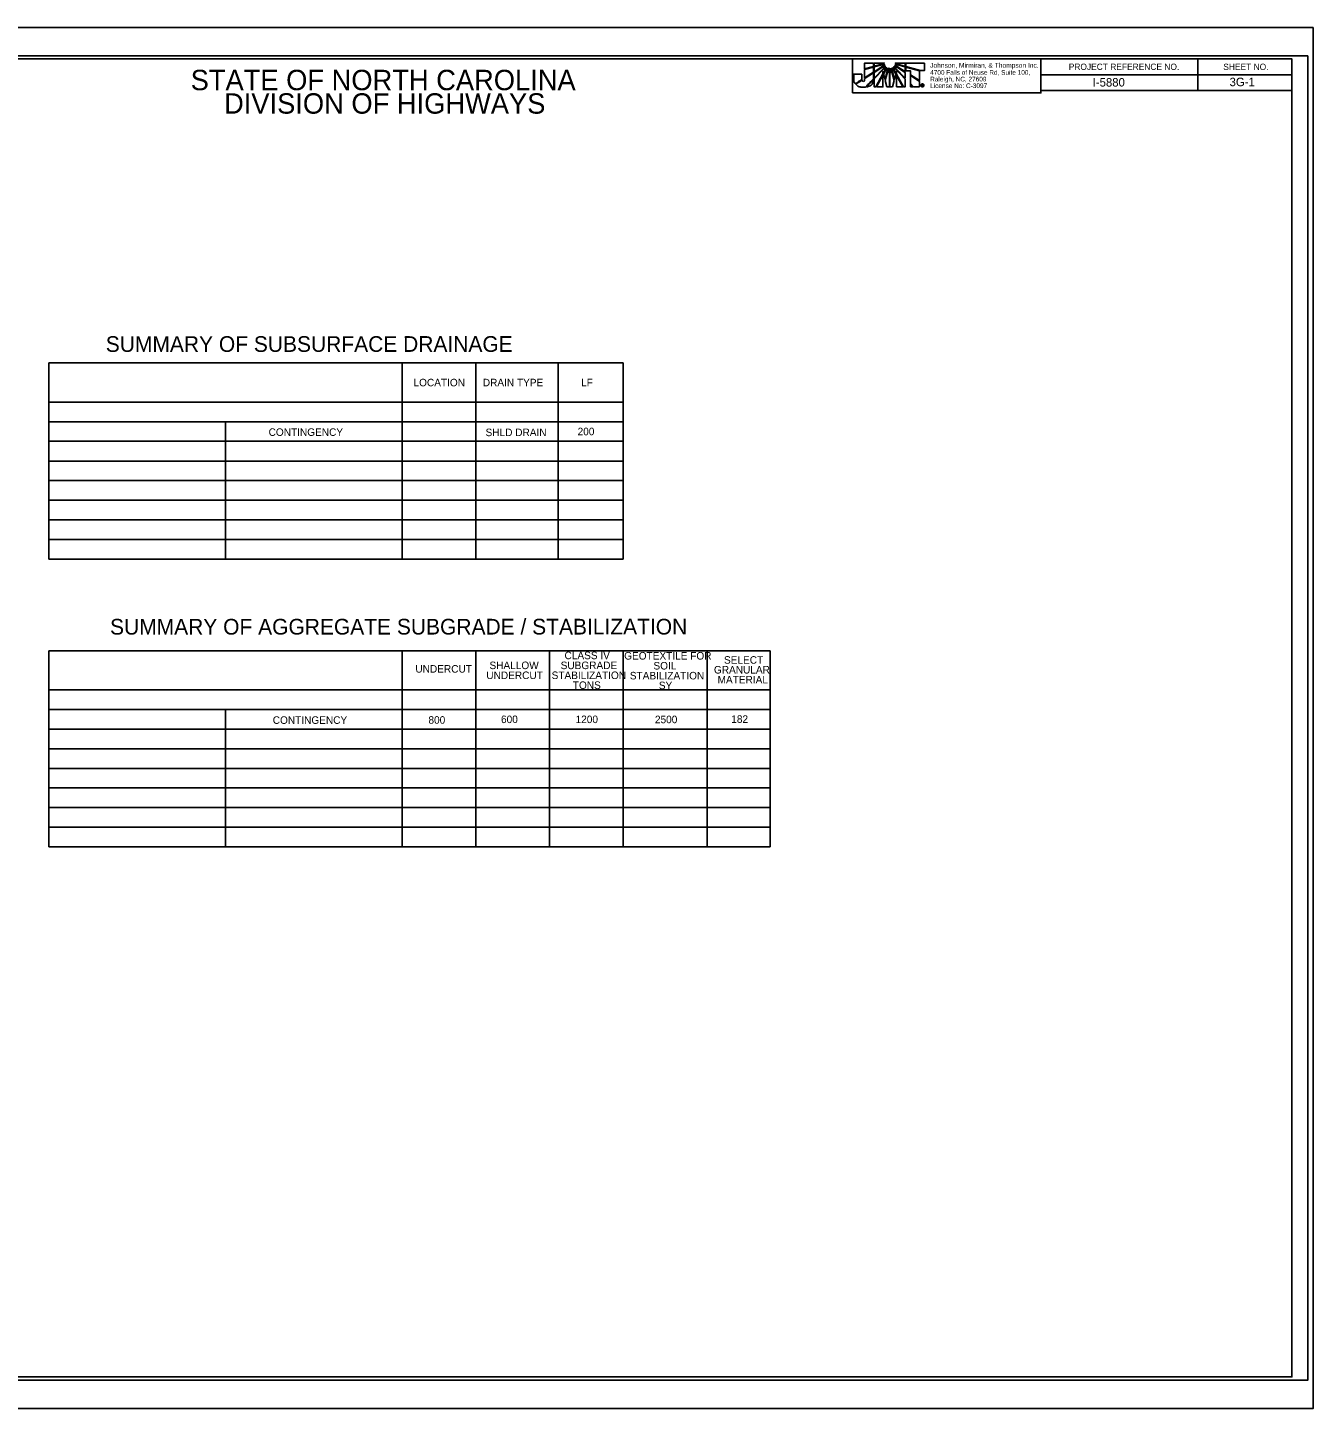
# Model space of a CAD drawing. Extents: x 573692 to 577281, y -53325 to -51406.
# Drawn here: x 576257 to 577281, y -53325 to -52225 of the extents above; entities that cross this region are included whole.
import ezdxf

# ---------------------------------------------------------------- set-up
doc = ezdxf.new("R2010")
doc.units = 0
for name, color, linetype in [('Exist Profile Cell', 7, 'Continuous'), ('Exist Vertical Profile Ground Line', 7, 'Continuous'), ('Exist Vertical Profile Horizontal Axis Label Major', 7, 'Continuous'), ('Prop Conc Island Cover', 7, 'Continuous'), ('Prop EOT', 7, 'Continuous'), ('Prop Horizontal Alignment', 7, 'Continuous'), ('Sheet North Arrow CELL', 7, 'Continuous')]:
    doc.layers.add(name, color=color, linetype=linetype)

msp = doc.modelspace()

# ---------------------------------------------------------------- linework, layer by layer
at = {"layer": 'Exist Profile Cell'}
msp.add_lwpolyline([(577280.6, -52224.8), (575596.6, -52224.8), (575596.6, -53324.8), (577280.6, -53324.8)], close=True, dxfattribs=at)
at = {"layer": 'Exist Vertical Profile Horizontal Axis Label Major'}
for p, q in [((577280.6, -52224.8), (575596.6, -52224.8)), ((575596.6, -53324.8), (577280.6, -53324.8))]:
    msp.add_line(p, q, dxfattribs=at)
at = {"layer": 'Prop Conc Island Cover'}
msp.add_lwpolyline([(577276.1, -52247.3), (575609.6, -52247.3), (575609.6, -53302.4), (577276.1, -53302.4)], close=True, dxfattribs=at)
at = {"layer": 'Prop EOT'}
for p, q in [((577188.6, -52249.9), (577188.6, -52274.9)), ((577063.6, -52262.4), (577263.6, -52262.4)), ((577063.6, -52274.9), (577263.6, -52274.9)), ((576516.2, -52491.9), (576516.2, -52491.9)), ((576497, -52492), (576497, -52492)), ((576504.9, -52492.1), (576504.9, -52492.1)), ((576523.2, -52492), (576523.2, -52492)), ((576497, -52721.3), (576497, -52721.3)), ((576504.9, -52721.4), (576504.9, -52721.4)), ((576516.2, -52721.2), (576516.2, -52721.2)), ((576523.2, -52721.3), (576523.2, -52721.3))]:
    msp.add_line(p, q, dxfattribs=at)
for points in [[(577263.6, -52249.8), (575763.6, -52249.8), (575763.6, -53299.8), (577263.6, -53299.8)], [(577063.6, -52249.8), (577263.6, -52249.8), (577263.6, -52274.9), (577063.6, -52274.9)]]:
    msp.add_lwpolyline(points, close=True, dxfattribs=at)
at = {"layer": 'Prop Horizontal Alignment'}
for p, q in [((576930.2, -52253.2), (576923.1, -52253.2)), ((576923.1, -52253.2), (576923.1, -52257.8)), ((576923.1, -52257.8), (576930.2, -52255.9)), ((576930.2, -52256.4), (576923.1, -52258.3)), ((576923.1, -52258.3), (576923.1, -52264.9)), ((576923.1, -52264.9), (576930.2, -52260.4)), ((576930.2, -52255.9), (576930.2, -52253.2)), ((576930.2, -52260.4), (576930.2, -52256.4)), ((576938.8, -52253.1), (576930.9, -52253.1)), ((576930.9, -52253.1), (576930.9, -52255.6)), ((576930.9, -52255.6), (576936.8, -52254)), ((576936.8, -52254.5), (576930.9, -52256.2)), ((576930.9, -52256.2), (576930.9, -52260)), ((576930.9, -52260), (576936.2, -52256.6)), ((576937, -52256.7), (576930.9, -52260.6)), ((576930.9, -52265), (576938.3, -52257.3)), ((576938.6, -52257.6), (576930.9, -52265.7)), ((576930.9, -52260.6), (576930.9, -52265)), ((576936.2, -52256.6), (576939.1, -52254.3)), ((576936.8, -52254), (576938.8, -52253.1)), ((576939.1, -52254.3), (576936.8, -52254.5)), ((576939.6, -52255.4), (576937, -52256.7)), ((576937.8, -52261.7), (576937.8, -52259.9)), ((576937.8, -52259.9), (576938.1, -52261.1)), ((576938.1, -52261.1), (576939.6, -52258.4)), ((576938.3, -52257.3), (576939.6, -52255.4)), ((576940.1, -52258.6), (576938.3, -52261.8)), ((576940.4, -52256.2), (576938.6, -52257.6)), ((576939.5, -52266), (576941.3, -52259)), ((576939.6, -52258.4), (576940.4, -52256.2)), ((576941.7, -52259.4), (576939.7, -52267)), ((576941.5, -52256.8), (576940.1, -52258.6)), ((576941.3, -52259), (576941.5, -52256.8)), ((576942.6, -52257.1), (576941.7, -52259.4)), ((576942.9, -52262.7), (576942.6, -52257.1)), ((576943.8, -52257.1), (576943.4, -52262.7)), ((576944.7, -52259.4), (576943.8, -52257.1)), ((576946.7, -52267.1), (576944.7, -52259.4)), ((576944.9, -52256.8), (576945.1, -52259.1)), ((576946.3, -52258.6), (576944.9, -52256.8)), ((576945.1, -52259.1), (576947, -52266.2)), ((576945.9, -52256.2), (576946.8, -52258.4)), ((576947.8, -52257.6), (576945.9, -52256.2)), ((576948.1, -52261.9), (576946.3, -52258.6)), ((576946.7, -52255.4), (576948.1, -52257.3)), ((576949.4, -52256.7), (576946.7, -52255.4)), ((576946.8, -52258.4), (576948.3, -52261.2)), ((576947.3, -52254.3), (576950.3, -52256.7)), ((576949.5, -52254.5), (576947.3, -52254.3)), ((576955.5, -52253.1), (576947.7, -52253.1)), ((576947.7, -52253.1), (576949.7, -52254)), ((576955.5, -52265.8), (576947.8, -52257.6)), ((576948.1, -52257.3), (576955.5, -52265)), ((576948.3, -52261.2), (576948.6, -52259.8)), ((576948.6, -52259.8), (576948.6, -52261.9)), ((576955.5, -52260.5), (576949.4, -52256.7)), ((576955.5, -52256.2), (576949.5, -52254.5)), ((576949.7, -52254), (576955.5, -52255.7)), ((576950.3, -52256.7), (576955.5, -52259.9)), ((576955.5, -52255.7), (576955.5, -52253.1)), ((576955.5, -52259.9), (576955.5, -52256.2)), ((576955.5, -52265), (576955.5, -52260.5)), ((576970.8, -52253.1), (576956, -52253.1)), ((576956, -52253.1), (576956, -52255.8)), ((576956, -52255.8), (576956, -52255.9)), ((576956, -52255.9), (576967.7, -52259.1)), ((576956, -52256.3), (576956, -52256.3)), ((576956, -52256.3), (576956, -52259.2)), ((576966.9, -52259.4), (576956, -52256.3)), ((576956, -52259.2), (576959.7, -52259.2)), ((576959.7, -52259.2), (576959.7, -52262.5)), ((576966.9, -52267.1), (576966.9, -52259.4)), ((576967.7, -52259.1), (576970.8, -52259.1)), ((576970.8, -52259.1), (576970.8, -52253.1)), ((576930.9, -52265.7), (576930.9, -52272.1)), ((576932.1, -52272.1), (576937.8, -52261.7)), ((576937.8, -52262.7), (576932.6, -52272.1)), ((576937.8, -52272.1), (576937.8, -52262.7)), ((576938.3, -52261.8), (576939.5, -52266)), ((576939.7, -52267), (576941, -52272)), ((576942.9, -52272), (576942.9, -52262.7)), ((576943.4, -52262.7), (576943.4, -52272)), ((576945.4, -52272), (576946.7, -52267.1)), ((576947, -52266.2), (576948.1, -52261.9)), ((576948.6, -52261.9), (576954.2, -52272.1)), ((576953.7, -52272), (576948.6, -52262.9)), ((576948.6, -52262.9), (576948.6, -52272)), ((576955.5, -52272.1), (576955.5, -52265.8)), ((576959.7, -52262.5), (576966.9, -52267.1)), ((576959.7, -52263.1), (576959.7, -52269.4)), ((576966.9, -52267.7), (576959.7, -52263.1)), ((576959.7, -52269.4), (576962.2, -52272)), ((576961.5, -52272), (576959.7, -52270.1)), ((576959.7, -52270.1), (576959.7, -52272)), ((576966.9, -52272), (576966.9, -52267.7)), ((576968.8, -52271.4), (576968.8, -52270.3)), ((576968.8, -52270.3), (576969.2, -52270.3)), ((576969, -52271.4), (576968.8, -52271.4)), ((576969.2, -52270.5), (576969, -52270.5)), ((576969, -52270.5), (576969, -52270.8)), ((576969, -52270.8), (576969.2, -52270.8)), ((576969.2, -52271), (576969, -52271)), ((576969, -52271), (576969, -52271.4)), ((576969.2, -52269.7), (576969.2, -52269.9)), ((576969.2, -52269.9), (576969.2, -52269.7)), ((576969.2, -52270.3), (576969.2, -52270.5)), ((576969.2, -52270.5), (576969.2, -52270.3)), ((576969.2, -52270.3), (576969.3, -52270.3)), ((576969.2, -52270.5), (576969.2, -52270.5)), ((576969.2, -52270.8), (576969.2, -52271)), ((576969.2, -52271), (576969.2, -52270.8)), ((576969.2, -52270.8), (576969.2, -52270.8)), ((576969.2, -52271), (576969.2, -52271)), ((576969.2, -52271.8), (576969.2, -52272)), ((576969.2, -52272), (576969.2, -52271.8)), ((576969.2, -52271.8), (576969.2, -52271.8)), ((576930.9, -52272.1), (576932.1, -52272.1)), ((576932.6, -52272.1), (576937.8, -52272.1)), ((576941, -52272), (576942.9, -52272)), ((576943.4, -52272), (576945.4, -52272)), ((576948.6, -52272), (576953.7, -52272)), ((576954.2, -52272.1), (576955.5, -52272.1)), ((576959.7, -52272), (576961.5, -52272)), ((576962.2, -52272), (576966.9, -52272)), ((576969.2, -52272), (576969.2, -52272))]:
    msp.add_line(p, q, dxfattribs=at)
msp.add_lwpolyline([(576913.6, -52276.9), (577063.6, -52276.9), (577063.6, -52249.8), (576913.6, -52249.8)], close=True, dxfattribs=at)
for points in [[(576923.1, -52257.8), (576930.2, -52255.9), (576930.2, -52253.2), (576923.1, -52253.2), (576923.1, -52257.8)], [(576923.1, -52264.9), (576930.2, -52260.4), (576930.2, -52256.4), (576923.1, -52258.3), (576923.1, -52264.9)], [(576936.8, -52254), (576938.8, -52253.1), (576930.9, -52253.1), (576930.9, -52255.6), (576936.8, -52254)], [(576930.9, -52256.2), (576930.9, -52260), (576936.2, -52256.6), (576939.1, -52254.3), (576936.8, -52254.5), (576930.9, -52256.2)], [(576930.9, -52260.6), (576930.9, -52265), (576938.3, -52257.3), (576939.6, -52255.4), (576937, -52256.7), (576930.9, -52260.6)], [(576940.4, -52256.2), (576938.6, -52257.6), (576930.9, -52265.7), (576930.9, -52272.1), (576932.1, -52272.1), (576937.8, -52261.7), (576937.8, -52259.9), (576938.1, -52261.1), (576939.6, -52258.4), (576940.4, -52256.2)], [(576941.5, -52256.8), (576940.1, -52258.6), (576938.3, -52261.8), (576939.5, -52266), (576941.3, -52259), (576941.5, -52256.8)], [(576941.7, -52259.4), (576939.7, -52267), (576941, -52272), (576942.9, -52272), (576942.9, -52262.7), (576942.6, -52257.1), (576941.7, -52259.4)], [(576943.8, -52257.1), (576943.4, -52262.7), (576943.4, -52272), (576945.4, -52272), (576946.7, -52267.1), (576944.7, -52259.4), (576943.8, -52257.1)], [(576944.9, -52256.8), (576945.1, -52259.1), (576947, -52266.2), (576948.1, -52261.9), (576946.3, -52258.6), (576944.9, -52256.8)], [(576945.9, -52256.2), (576946.8, -52258.4), (576948.3, -52261.2), (576948.6, -52259.8), (576948.6, -52261.9), (576954.2, -52272.1), (576955.5, -52272.1), (576955.5, -52265.8), (576947.8, -52257.6), (576945.9, -52256.2)], [(576946.7, -52255.4), (576948.1, -52257.3), (576955.5, -52265), (576955.5, -52260.5), (576949.4, -52256.7), (576946.7, -52255.4)], [(576947.3, -52254.3), (576950.3, -52256.7), (576955.5, -52259.9), (576955.5, -52256.2), (576949.5, -52254.5), (576947.3, -52254.3)], [(576949.7, -52254), (576955.5, -52255.7), (576955.5, -52253.1), (576947.7, -52253.1), (576949.7, -52254)], [(576970.8, -52253.1), (576956, -52253.1), (576956, -52255.8), (576956, -52255.9), (576967.7, -52259.1), (576970.8, -52259.1), (576970.8, -52253.1)], [(576956, -52256.3), (576956, -52256.3), (576956, -52259.2), (576959.7, -52259.2), (576959.7, -52262.5), (576966.9, -52267.1), (576966.9, -52259.4), (576956, -52256.3)], [(576932.6, -52272.1), (576937.8, -52272.1), (576937.8, -52262.7), (576932.6, -52272.1)], [(576948.6, -52272), (576953.7, -52272), (576948.6, -52262.9), (576948.6, -52272)], [(576959.7, -52263.1), (576959.7, -52269.4), (576962.2, -52272), (576966.9, -52272), (576966.9, -52267.7), (576959.7, -52263.1), (576959.7, -52263.1)], [(576959.7, -52272), (576959.7, -52272), (576961.5, -52272), (576959.7, -52270.1), (576959.7, -52272)], [(576969.7, -52271.1), (576969.7, -52271.2), (576969.7, -52271.2), (576969.7, -52271.3), (576969.7, -52271.4), (576969.5, -52271.4)]]:
    msp.add_lwpolyline(points, dxfattribs=at)
for points, degree in [([(576921.1, -52261.9), (576921.1, -52261.9), (576914.6, -52261.9), (576914.6, -52261.9), (576914.6, -52261.9), (576914.6, -52266), (576914.6, -52266), (576914.6, -52266), (576914.6, -52266.4), (576914.6, -52266.4), (576914.6, -52267.7), (576915.1, -52268.7), (576915.8, -52269.5), (576915.8, -52269.5), (576921.1, -52266.3), (576921.1, -52266.2), (576921.1, -52266.2), (576921.1, -52261.9), (576921.1, -52261.9)], 3), ([(576922.1, -52267.7), (576921.7, -52267.7), (576921.4, -52267.5), (576921.2, -52266.7), (576921.2, -52266.7), (576916.2, -52269.8), (576916.2, -52269.8), (576917.7, -52271.5), (576920.2, -52272.4), (576922.3, -52272.4), (576922.9, -52272.4), (576923.3, -52272.4), (576923.8, -52272.3), (576923.8, -52272.3), (576930.2, -52265.7), (576930.2, -52265.7), (576930.2, -52265.7), (576930.2, -52261), (576930.2, -52261), (576930.2, -52261), (576923.1, -52265.5), (576923.1, -52265.5), (576923.1, -52267.3), (576922.7, -52267.7), (576922.1, -52267.7)], 3), ([(576922.1, -52267.7), (576921.7, -52267.7), (576921.4, -52267.5), (576921.2, -52266.7), (576921.2, -52266.7), (576916.2, -52269.8), (576916.2, -52269.8), (576917.7, -52271.5), (576920.2, -52272.4), (576922.3, -52272.4), (576922.9, -52272.4), (576923.3, -52272.4), (576923.8, -52272.3), (576923.8, -52272.3), (576930.2, -52265.7), (576930.2, -52265.7), (576930.2, -52265.7), (576930.2, -52261), (576930.2, -52261), (576930.2, -52261), (576923.1, -52265.5), (576923.1, -52265.5), (576923.1, -52267.3), (576922.7, -52267.7), (576922.1, -52267.7)], 3), ([(576930.2, -52266.5), (576930.2, -52266.5), (576924.7, -52272.1), (576924.7, -52272.1), (576927.4, -52271.5), (576930, -52269.7), (576930.2, -52266.5)], 3), ([(576969.2, -52272), (576968.9, -52272), (576968.6, -52271.9), (576968.4, -52271.7), (576968.1, -52271.5), (576968, -52271.2), (576968, -52270.8), (576968, -52270.5), (576968.1, -52270.2), (576968.4, -52270), (576968.6, -52269.8), (576968.9, -52269.7), (576969.2, -52269.7)], 3), ([(576969.2, -52269.9), (576969, -52269.9), (576968.7, -52270), (576968.5, -52270.2), (576968.4, -52270.3), (576968.3, -52270.6), (576968.3, -52270.8), (576968.3, -52271.1), (576968.4, -52271.3), (576968.5, -52271.5), (576968.7, -52271.7), (576969, -52271.8), (576969.2, -52271.8)], 3), ([(576969.2, -52269.7), (576969.6, -52269.7), (576969.8, -52269.8), (576970.1, -52270), (576970.3, -52270.2), (576970.4, -52270.5), (576970.4, -52270.8)], 3), ([(576969.2, -52271.8), (576969.5, -52271.8), (576969.7, -52271.7), (576969.9, -52271.5), (576970.1, -52271.3), (576970.2, -52271.1), (576970.2, -52270.8), (576970.2, -52270.6), (576970.1, -52270.3), (576969.9, -52270.2), (576969.7, -52270), (576969.5, -52269.9), (576969.2, -52269.9)], 3), ([(576969.2, -52270.8), (576969.4, -52270.8), (576969.5, -52270.7), (576969.5, -52270.6), (576969.5, -52270.5), (576969.4, -52270.5), (576969.2, -52270.5)], 3), ([(576970.4, -52270.8), (576970.4, -52271.2), (576970.3, -52271.5), (576970.1, -52271.7), (576969.8, -52271.9), (576969.6, -52272), (576969.2, -52272)], 3), ([(576969.4, -52271), (576969.4, -52271), (576969.3, -52271), (576969.2, -52271)], 2), ([(576969.3, -52270.3), (576969.6, -52270.3), (576969.7, -52270.4), (576969.7, -52270.6), (576969.7, -52270.7), (576969.7, -52270.8), (576969.6, -52270.9)], 3), ([(576969.5, -52271.4), (576969.5, -52271.3), (576969.5, -52271.3), (576969.5, -52271.2), (576969.5, -52271.1), (576969.4, -52271), (576969.4, -52271)], 3), ([(576969.6, -52270.9), (576969.6, -52270.9), (576969.7, -52271), (576969.7, -52271.1)], 2)]:
    msp.add_open_spline(points, degree=degree, dxfattribs=at)
at = {"layer": 'Sheet North Arrow CELL'}
for p, q in [((576273.4, -52491.9), (576730.8, -52491.9)), ((576273.4, -52491.9), (576273.4, -52648.2)), ((576554.9, -52491.9), (576554.9, -52648.2)), ((576613.5, -52491.9), (576613.5, -52648.2)), ((576679.1, -52491.3), (576679.1, -52647.6)), ((576730.8, -52491.9), (576730.8, -52648.2)), ((576273.4, -52523.2), (576730.8, -52523.2)), ((576273.4, -52538.8), (576730.8, -52538.8)), ((576414.2, -52538.8), (576414.2, -52648.2)), ((576273.4, -52554.4), (576730.8, -52554.4)), ((576273.4, -52570.1), (576730.8, -52570.1)), ((576273.4, -52585.7), (576730.8, -52585.7)), ((576273.4, -52601.3), (576730.8, -52601.3)), ((576273.4, -52616.9), (576730.8, -52616.9)), ((576273.4, -52632.6), (576730.8, -52632.6)), ((576273.4, -52648.2), (576730.8, -52648.2)), ((576273.4, -52648.2), (576730.8, -52648.2)), ((576273.4, -52721.2), (576848, -52721.2)), ((576273.4, -52721.2), (576273.4, -52877.5)), ((576554.9, -52721.2), (576554.9, -52877.5)), ((576613.5, -52721.2), (576613.5, -52877.5)), ((576672.2, -52721.2), (576672.2, -52877.5)), ((576730.8, -52721.2), (576730.8, -52877.5)), ((576797.8, -52721.2), (576797.8, -52877.5)), ((576848, -52721.2), (576848, -52877.5)), ((576273.4, -52752.5), (576848, -52752.5)), ((576273.4, -52768.1), (576848, -52768.1)), ((576414.2, -52768.1), (576414.2, -52877.5)), ((576273.4, -52783.7), (576848, -52783.7)), ((576273.4, -52799.4), (576848, -52799.4)), ((576273.4, -52815), (576848, -52815)), ((576273.4, -52830.6), (576848, -52830.6)), ((576273.4, -52846.2), (576848, -52846.2)), ((576273.4, -52861.9), (576848, -52861.9)), ((576273.4, -52877.5), (576848, -52877.5))]:
    msp.add_line(p, q, dxfattribs=at)

# ---------------------------------------------------------------- texts
at = {"layer": 'Exist Vertical Profile Ground Line'}
for s, p in [('I-5880', (577104.9, -52271.8)), ('3G-1', (577213.9, -52271.5))]:
    msp.add_text(s, height=6.75, dxfattribs=at).set_placement(p)
at = {"layer": 'Prop EOT'}
for s, height, p in [('STATE OF NORTH CAROLINA', 16.25, (576386.4, -52274.7)), ('PROJECT REFERENCE NO.', 5, (577085.8, -52258.5)), ('SHEET NO.', 5, (577208.9, -52258.6)), ('DIVISION OF HIGHWAYS', 16.25, (576413, -52293.4)), ('LOCATION', 6, (576563.9, -52510.6)), ('DRAIN TYPE', 6, (576619.1, -52510.6)), ('LF', 6, (576697.4, -52510.6)), ('CONTINGENCY', 6, (576448.5, -52550.1)), ('SHLD DRAIN', 6, (576621.3, -52550.3)), ('200', 6, (576694.6, -52549.6)), ('CLASS IV', 6, (576684.2, -52728)), ('GEOTEXTILE FOR', 6, (576731.7, -52728.3)), ('UNDERCUT', 6, (576565.4, -52738.7)), ('SHALLOW', 6, (576624.4, -52735.9)), ('SUBGRADE', 6, (576681.1, -52735.9)), ('SOIL', 6, (576755, -52736.2)), ('GRANULAR', 6, (576803.2, -52739.4)), ('SELECT', 6, (576811.2, -52731.6)), ('UNDERCUT', 6, (576621.9, -52743.8)), ('STABILIZATION', 6, (576673.9, -52743.8)), ('STABILIZATION', 6, (576736.2, -52744.1)), ('MATERIAL', 6, (576806.1, -52747.3)), ('TONS', 6, (576690.8, -52751.7)), ('SY', 6, (576759.3, -52751.9)), ('CONTINGENCY', 6, (576451.8, -52779.5)), ('800', 6, (576575.8, -52779.4)), ('600', 6, (576633.6, -52778.9)), ('1200', 6, (576693, -52778.9)), ('2500', 6, (576756.2, -52779)), ('182', 6, (576817, -52778.7))]:
    msp.add_text(s, height=height, dxfattribs=at).set_placement(p)
for s, p in [('SUMMARY OF SUBSURFACE DRAINAGE', (576318.8, -52483.2)), ('SUMMARY OF AGGREGATE SUBGRADE / STABILIZATION', (576322.2, -52708.4))]:
    msp.add_text(s, height=12.5, rotation=0.0119, dxfattribs=at).set_placement(p)
at = {"layer": 'Prop Horizontal Alignment'}
for s, height, p in [('Johnson, Mirmiran, & Thompson Inc.', 3.831, (576975.4, -52256.8)), ('4700 Falls of Neuse Rd, Suite 100, ', 3.722, (576975.4, -52262.4)), ('Raleigh, NC, 27609', 3.722, (576975.4, -52267.7)), ('License No: C-3097', 3.722, (576975.4, -52273))]:
    msp.add_text(s, height=height, rotation=360, dxfattribs=at).set_placement(p)

doc.saveas('drawing.dxf')
